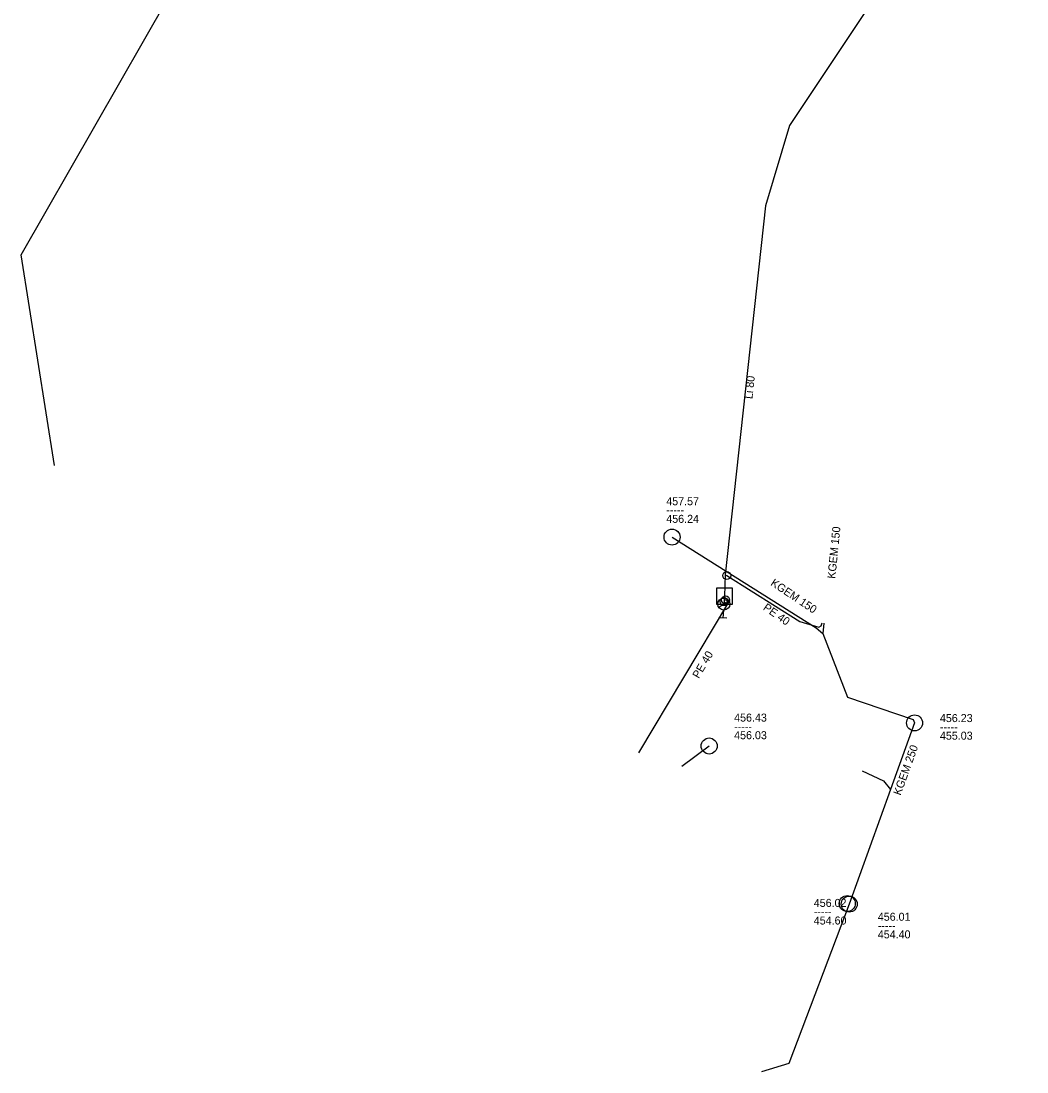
# Model space of a CAD drawing. Extents: x -755931 to -755358, y -1113840 to -1113401.
# Drawn here: x -755890.4 to -755764.7, y -1113840.4 to -1113709.1 of the extents above; entities that cross this region are included whole.
import ezdxf

# ---------------------------------------------------------------- set-up
doc = ezdxf.new("R2010")
doc.units = 0
doc.layers.add('Level 0', color=7, linetype='Continuous')

msp = doc.modelspace()

# ---------------------------------------------------------------- linework, layer by layer
at = {"layer": 'Level 0'}
for p, q in [((-755890.41, -1113738.31), (-755832.53, -1113637.35)), ((-755764.72, -1113677.61), (-755794.41, -1113722.14)), ((-755794.41, -1113722.14), (-755797.41, -1113732.21)), ((-755797.41, -1113732.21), (-755802.42, -1113778.32)), ((-755886.24, -1113764.66), (-755890.41, -1113738.31)), ((-755809.07, -1113773.59), (-755791.06, -1113784.93)), ((-755802.42, -1113778.32), (-755802.52, -1113780.96)), ((-755802.42, -1113778.32), (-755802.23, -1113778.4)), ((-755802.23, -1113778.4), (-755793.12, -1113784.14)), ((-755801.52, -1113779.96), (-755803.52, -1113779.96)), ((-755803.52, -1113779.96), (-755803.52, -1113781.96)), ((-755801.52, -1113781.96), (-755801.52, -1113779.96)), ((-755802.01, -1113781.73), (-755813.27, -1113800.57)), ((-755803.52, -1113781.96), (-755801.52, -1113781.96)), ((-755801.98, -1113781.54), (-755803.22, -1113782.38)), ((-755802.57, -1113781.66), (-755802.6, -1113781.96)), ((-755802.54, -1113781.41), (-755802.57, -1113781.66)), ((-755802.52, -1113780.96), (-755802.54, -1113781.41)), ((-755802.54, -1113781.41), (-755802.38, -1113781.45)), ((-755802.38, -1113781.45), (-755802.14, -1113781.51)), ((-755802.14, -1113781.51), (-755802.01, -1113781.73)), ((-755802.65, -1113782.71), (-755802.72, -1113783.71)), ((-755802.22, -1113783.74), (-755803.21, -1113783.67)), ((-755793.12, -1113784.14), (-755790.72, -1113784.85)), ((-755790.72, -1113784.85), (-755790.44, -1113784.69)), ((-755790.44, -1113784.69), (-755790.3, -1113784.31)), ((-755790.09, -1113784.36), (-755790.22, -1113785.66)), ((-755791.06, -1113784.93), (-755790.22, -1113785.66)), ((-755790.22, -1113785.66), (-755787.15, -1113793.61)), ((-755787.15, -1113793.61), (-755778.95, -1113796.38)), ((-755778.95, -1113796.38), (-755778.76, -1113796.82)), ((-755778.76, -1113796.82), (-755781.77, -1113805.15)), ((-755804.43, -1113799.7), (-755807.84, -1113802.25)), ((-755785.33, -1113802.82), (-755782.66, -1113804.04)), ((-755782.66, -1113804.04), (-755781.77, -1113805.15)), ((-755781.77, -1113805.15), (-755786.93, -1113819.46)), ((-755786.93, -1113819.46), (-755794.46, -1113839.39)), ((-755794.46, -1113839.39), (-755797.9, -1113840.44))]:
    msp.add_line(p, q, dxfattribs=at)
for centre, radius in [((-755809.07, -1113773.59), 1), ((-755802.23, -1113778.4), 0.5), ((-755802.6, -1113781.96), 0.75), ((-755802.57, -1113781.66), 0.5), ((-755802.38, -1113781.45), 0.5), ((-755778.76, -1113796.82), 1), ((-755804.43, -1113799.7), 1), ((-755787.17, -1113819.39), 1), ((-755786.93, -1113819.46), 1)]:
    msp.add_circle(centre, radius, dxfattribs=at)

# ---------------------------------------------------------------- texts
for s, rotation, p in [('Li 80', 83.799, (-755799.03, -1113756.37)), ('KGEM 150', 84.289, (-755788.67, -1113778.83)), ('KGEM 150', 326.238, (-755796.84, -1113779.55)), ('PE 40', 325.246, (-755797.78, -1113782.61)), ('PE 40', 59.483, (-755805.73, -1113791.34)), ('KGEM 250', 70.171, (-755780.52, -1113805.94))]:
    msp.add_text(s, height=1, rotation=rotation, dxfattribs=at).set_placement(p)
for s, p in [('457.57', (-755809.79, -1113769.61)), ('-----', (-755809.79, -1113770.71)), ('456.24', (-755809.79, -1113771.81)), ('456.43', (-755801.31, -1113796.65)), ('456.23', (-755775.6, -1113796.71)), ('456.03', (-755801.31, -1113798.85)), ('-----', (-755801.31, -1113797.75)), ('-----', (-755775.6, -1113797.81)), ('455.03', (-755775.6, -1113798.91)), ('456.02', (-755791.36, -1113819.81)), ('454.60', (-755791.36, -1113822.01)), ('-----', (-755791.36, -1113820.91)), ('456.01', (-755783.36, -1113821.54)), ('454.40', (-755783.36, -1113823.74)), ('-----', (-755783.36, -1113822.64))]:
    msp.add_text(s, height=1, dxfattribs=at).set_placement(p)

doc.saveas('drawing.dxf')
